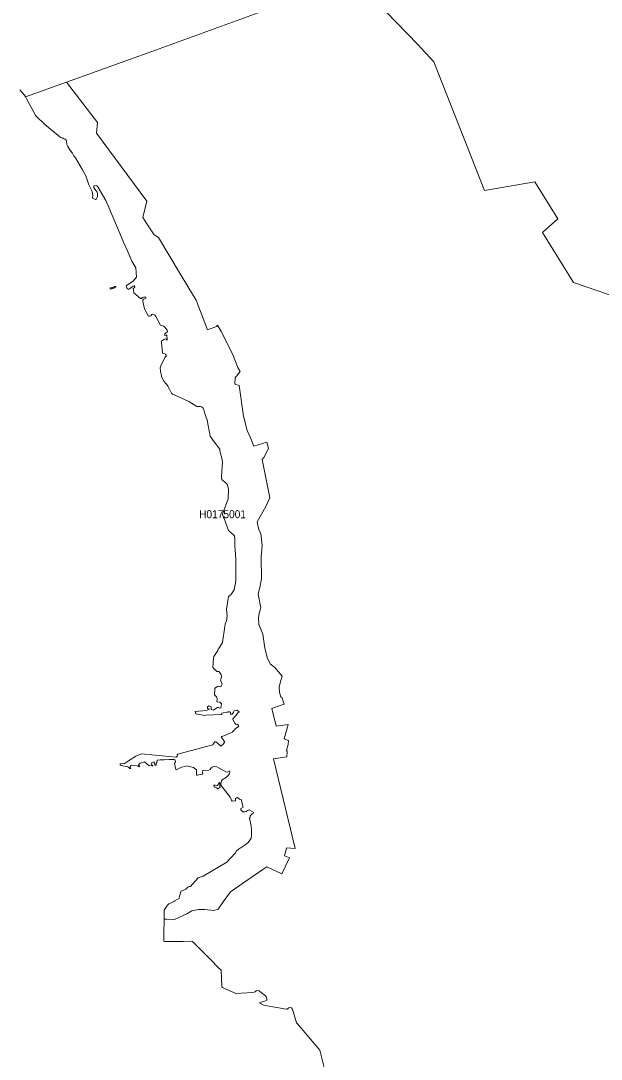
# Model space of a CAD drawing. Extents: x 369010 to 739155, y 6377141 to 6616555.
# Drawn here: x 408273 to 415523, y 6515962 to 6528935 of the extents above; entities that cross this region are included whole.
import ezdxf
from ezdxf.enums import TextEntityAlignment as Align

# ---------------------------------------------------------------- set-up
doc = ezdxf.new("R2010")
doc.units = 0
doc.header["$LTSCALE"] = 40
doc.layers.add('1', color=7, linetype='Continuous', lineweight=13)
doc.layers.add('2', color=7, linetype='Continuous')

msp = doc.modelspace()

# ---------------------------------------------------------------- linework, layer by layer
at = {"layer": '1'}
for points in [[(408261.96, 6528071.2), (408317.41, 6528003.84), (408332.3, 6527985.63), (408844.54, 6528170.01), (409956.56, 6528570.03), (412430.18, 6529472.36), (413231.39, 6528636.89), (413431.98, 6528420.25), (414063.54, 6526816.02), (414694.11, 6526922.93), (414982.91, 6526461.01), (414789.77, 6526292.2), (415176.55, 6525665.1), (415772.53, 6525459.71)], [(415772.53, 6525459.71), (415176.55, 6525665.1), (414789.77, 6526292.2), (414982.91, 6526461.01), (414694.11, 6526922.93), (414063.54, 6526816.02), (413431.98, 6528420.25), (413231.39, 6528636.89), (412430.18, 6529472.36), (409956.56, 6528570.03), (408844.54, 6528170.01)], [(408844.54, 6528170.01), (408332.3, 6527985.63), (408339.75, 6527966.77), (408462.22, 6527749.13), (408573.94, 6527637.91), (408758.97, 6527486.81), (408774.2, 6527476.71), (408789.75, 6527469.76), (408801.34, 6527468.27), (408816.9, 6527461.48), (408827.49, 6527454.2), (408839.41, 6527441.79), (408844.37, 6527430.86), (408850.16, 6527387.83), (408860.92, 6527363.84), (408893.53, 6527312.2), (408917.69, 6527280.26), (408936.23, 6527248.98), (408956.25, 6527223.32), (409044.47, 6527072.22), (409084.19, 6526996.09), (409123.91, 6526886.03), (409164.95, 6526804.43), (409171.9, 6526757.1), (409169.75, 6526720.03), (409176.21, 6526716.71), (409198.38, 6526705.13), (409205.5, 6526701.49), (409212.45, 6526702.32), (409220.06, 6526711.75), (409228.01, 6526729.46), (409233.14, 6526747.66), (409232.48, 6526776.63), (409228.34, 6526791.36), (409223.71, 6526800.46), (409214.6, 6526812.05), (409186.8, 6526849.45), (409184.48, 6526866.83), (409185.97, 6526871.13), (409192.09, 6526874.11), (409212.78, 6526876.92), (409223.04, 6526871.96), (409234.79, 6526859.54), (409335.75, 6526689.57), (409378.29, 6526592.59), (409547.43, 6526188.59), (409550.74, 6526179.16), (409603.54, 6526069.26), (409661.79, 6525930.24), (409710.45, 6525850.14), (409718.73, 6525732.3), (409693.74, 6525703.66), (409675.37, 6525681.32), (409592.45, 6525629.85), (409590.3, 6525621.74), (409592.78, 6525609.49), (409602.54, 6525589.96), (409606.19, 6525586.32), (409614.13, 6525583.01), (409624.39, 6525583.34), (409643.42, 6525593.6), (409648.55, 6525599.73), (409664.61, 6525613.47), (409678.01, 6525619.26), (409689.6, 6525622.07), (409695.23, 6525620.75), (409699.36, 6525617.44), (409698.87, 6525610.49), (409688.11, 6525598.57), (409676.03, 6525590.96), (409686.79, 6525536.67), (409767.72, 6525466), (409774.34, 6525463.85), (409781.12, 6525466.33), (409792.38, 6525477.92), (409806.61, 6525484.04), (409820.68, 6525485.86), (409832.26, 6525483.38), (409836.57, 6525478.25), (409835.24, 6525469.64), (409805.78, 6525456.24), (409797.84, 6525446.14), (409795.69, 6525434.89), (409800.32, 6525413.37), (409816.54, 6525336.25), (409858.74, 6525260.94), (409864.87, 6525250.68), (409871.49, 6525245.05), (409880.43, 6525244.23), (409895.98, 6525251.18), (409911.21, 6525263.76), (409919.98, 6525267.89), (409931.07, 6525267.4), (409948.78, 6525257.96), (409958.54, 6525241.41), (410018.95, 6525131.85), (410031.86, 6525127.88), (410056.19, 6525118.61), (410071.25, 6525108.35), (410101.7, 6525070.28)], [(410985.83, 6524604.55), (410917.8, 6524774.86), (410777.29, 6525055.05), (410731.94, 6525130.69), (410716.88, 6525115.63), (410607.15, 6525073.92), (410463.66, 6525443.49), (410357.74, 6525613.8), (410263.07, 6525772.68), (409994.62, 6526229.64), (409937.86, 6526259.92), (409873.64, 6526362.04), (409798, 6526475.58), (409847.16, 6526679.97), (409220.23, 6527529.01), (409231.48, 6527665.22), (408845.69, 6528168.35), (408844.54, 6528170.01)], [(408844.54, 6528170.01), (408845.69, 6528168.35), (409231.48, 6527665.22), (409220.23, 6527529.01), (409847.16, 6526679.97), (409798, 6526475.58), (409873.64, 6526362.04), (409937.86, 6526259.92), (409994.62, 6526229.64), (410263.07, 6525772.68), (410357.74, 6525613.8), (410463.66, 6525443.49), (410607.15, 6525073.92), (410716.88, 6525115.63), (410731.94, 6525130.69), (410777.29, 6525055.05), (410917.8, 6524774.86), (410985.83, 6524604.55), (411013.96, 6524555.73), (410950.24, 6524472.81), (410945.94, 6524395.85), (410999.23, 6524379.63), (411055.34, 6523994.34), (411102.67, 6523817.08), (411144.05, 6523725.23), (411182.61, 6523620.14), (411345.47, 6523671.94), (411367.64, 6523593.49), (411309.88, 6523479.46), (411286.22, 6523453.47), (411382.54, 6522976.66), (411333.39, 6522867.92), (411225.31, 6522675.27), (411244.51, 6522576.14), (411269.67, 6522527.97), (411287.38, 6522379.85), (411277.11, 6522234.7), (411279.93, 6521962.94), (411259.24, 6521856.36), (411240.04, 6521776.26), (411260.73, 6521665.2), (411271.16, 6521601.48), (411251.79, 6521534.12), (411243.02, 6521474.87), (411247.49, 6521391.95), (411296.31, 6521272.46), (411319.98, 6521096.2), (411355.4, 6520968.93), (411393.96, 6520899.25), (411447.25, 6520854.89), (411538.94, 6520748.14), (411516.43, 6520680.62), (411501.7, 6520608.13), (411504.68, 6520547.39), (411520.9, 6520486.65), (411532.82, 6520483.67), (411555, 6520422.93), (411562.44, 6520397.77), (411407.03, 6520342.99), (411461.65, 6520123.37), (411611.27, 6520142.57), (411560.95, 6519963.32), (411615.74, 6519944.13), (411614.25, 6519893.81), (411590.58, 6519819.67), (411602.33, 6519806.43), (411595.05, 6519741.22), (411429.21, 6519716.06), (411701.3, 6518595.1), (411590.25, 6518602.55), (411581.31, 6518550.75), (411568.07, 6518503.41), (411627.32, 6518479.58), (411532.65, 6518277.34), (411346.13, 6518366.21), (411310.55, 6518339.56), (411041.77, 6518157.51), (410893.64, 6518052.42), (410800.63, 6517926.8), (410740.05, 6517836.6), (410683.78, 6517818.89), (410572.73, 6517832.13), (410493.62, 6517833.78), (410409.21, 6517817.57), (410348.47, 6517780.49), (410194.55, 6517706.51), (410092.6, 6517712.14), (410062.15, 6517713.79), (410061.32, 6517528.93), (410058.01, 6517436.57), (410067.11, 6517433.93), (410300.14, 6517432.77), (410399.94, 6517438.56), (410416.99, 6517431.44), (410530.03, 6517322.21), (410643.56, 6517207.68), (410744.36, 6517105.4), (410777.13, 6517076.44), (410785.4, 6516868.57), (410794.17, 6516856.65)], [(410101.7, 6525070.28), (410105.68, 6525060.19), (410104.68, 6525051.08), (410098.73, 6525043.97), (410080.35, 6525032.38), (410070.92, 6525021.13), (410066.29, 6525011.2), (410068.11, 6525005.9), (410076.38, 6525001.93), (410089.79, 6525006.56), (410095.25, 6525011.2), (410103.36, 6524946.48), (410083.5, 6524960.22), (410067.94, 6524958.07), (410058.51, 6524954.1), (410031.86, 6524932.58), (410029.21, 6524923.15), (410030.04, 6524911.73), (410041.3, 6524791.24), (410044.61, 6524784.12), (410056.19, 6524778), (410074.89, 6524773.53), (410082.18, 6524767.08), (410087.31, 6524756.98), (410087.64, 6524745.23), (410078.2, 6524730.83), (410027.89, 6524636.66), (410014.48, 6524599.59), (410018.29, 6524559.04), (410029.21, 6524497.8), (410034.18, 6524479.1), (410060.99, 6524433.26), (410087.64, 6524399.33), (410103.86, 6524377.48), (410130.01, 6524332.96), (410147.71, 6524298.54), (410155.99, 6524281.99), (410168.57, 6524271.06), (410195.05, 6524256.5), (410200.18, 6524256.17), (410371.81, 6524178.21), (410473.92, 6524117.14), (410512.32, 6524117.14), (410529.86, 6524111.68), (410551.54, 6524094.97), (410559.16, 6524075.77), (410569.58, 6524041.67), (410586.63, 6523978.62), (410600.37, 6523949.65), (410611.46, 6523880.14), (410639.1, 6523744.93), (410687.42, 6523674.59), (410760.41, 6523584.39), (410759.91, 6523561.88), (410762.07, 6523546.65), (410786.73, 6523452.48), (410789.04, 6523438.08), (410793.68, 6523427.16), (410778.28, 6523241.63), (410779.77, 6523218.46), (410785.07, 6523206.54), (410794.5, 6523198.1), (410850.61, 6523145.64), (410867.99, 6523086.22), (410863.02, 6522964.74), (410795.33, 6522783.18), (410792.85, 6522771.27), (410794.67, 6522758.19), (410806.59, 6522728.57), (410813.37, 6522719.13), (410869.15, 6522566.87), (410940.48, 6522502.49), (410944.95, 6522456.48), (410947.76, 6522366.28), (410951.07, 6522327.88), (410953.22, 6522264.82), (410957.03, 6522207.56), (410957.03, 6522171.98), (410957.86, 6521939.61), (410939.98, 6521827.06), (410897.78, 6521762.19), (410885.03, 6521755.73), (410869.15, 6521740.84), (410842.5, 6521586.59), (410851.6, 6521497.55), (410843.16, 6521434.99), (410827.11, 6521407.02), (410823.8, 6521392.12), (410820.65, 6521366.8), (410792.35, 6521168.03), (410753.79, 6521105.96), (410739.06, 6521083.46), (410734.59, 6521068.73), (410682.29, 6520991.77), (410679.98, 6520976.37), (410671.7, 6520855.56), (410719.86, 6520807.23), (410730.29, 6520804.58), (410747.34, 6520805.57), (410757.1, 6520797.96)], [(411153.98, 6518796.36), (411155.97, 6518757.13), (411151.17, 6518725.52), (411144.05, 6518711.29), (411134.12, 6518699.7), (411114.59, 6518671.4), (411086.78, 6518648.06), (410986.16, 6518582.52), (410967.46, 6518563.82), (410951.24, 6518537.51), (410848.29, 6518422.15), (410550.88, 6518249.7), (410488.49, 6518226.86), (410416.99, 6518147.25), (410391.34, 6518120.6), (410376.28, 6518119.78), (410360.88, 6518110.84), (410334.73, 6518085.85), (410274.82, 6518063.34), (410272.34, 6518055.06), (410252.64, 6517981.91), (410253.47, 6517973.97), (410197.53, 6517940.87), (410192.57, 6517937.22), (410134.64, 6517907.27), (410123.55, 6517902.97), (410103.53, 6517885.92), (410071.09, 6517838.42), (410062.48, 6517826.01), (410062.15, 6517713.79), (410092.6, 6517712.14), (410194.55, 6517706.51), (410348.47, 6517780.49), (410409.21, 6517817.57), (410493.62, 6517833.78), (410572.73, 6517832.13), (410683.78, 6517818.89), (410740.05, 6517836.6), (410800.63, 6517926.8), (410893.64, 6518052.42), (411041.77, 6518157.51), (411310.55, 6518339.56), (411346.13, 6518366.21), (411532.65, 6518277.34), (411627.32, 6518479.58), (411568.07, 6518503.41), (411581.31, 6518550.75), (411590.25, 6518602.55), (411701.3, 6518595.1), (411429.21, 6519716.06), (411595.05, 6519741.22), (411602.33, 6519806.43), (411590.58, 6519819.67), (411614.25, 6519893.81), (411615.74, 6519944.13), (411560.95, 6519963.32), (411611.27, 6520142.57), (411461.65, 6520123.37), (411407.03, 6520342.99), (411562.44, 6520397.77), (411555, 6520422.93), (411532.82, 6520483.67), (411520.9, 6520486.65), (411504.68, 6520547.39), (411501.7, 6520608.13), (411516.43, 6520680.62), (411538.94, 6520748.14), (411447.25, 6520854.89), (411393.96, 6520899.25), (411355.4, 6520968.93), (411319.98, 6521096.2), (411296.31, 6521272.46), (411247.49, 6521391.95), (411243.02, 6521474.87), (411251.79, 6521534.12), (411271.16, 6521601.48), (411260.73, 6521665.2), (411240.04, 6521776.26), (411259.24, 6521856.36), (411279.93, 6521962.94), (411277.11, 6522234.7), (411287.38, 6522379.85), (411269.67, 6522527.97), (411244.51, 6522576.14), (411225.31, 6522675.27), (411333.39, 6522867.92), (411382.54, 6522976.66), (411286.22, 6523453.47), (411309.88, 6523479.46), (411367.64, 6523593.49), (411345.47, 6523671.94), (411182.61, 6523620.14), (411144.05, 6523725.23), (411102.67, 6523817.08), (411055.34, 6523994.34), (410999.23, 6524379.63), (410945.94, 6524395.85), (410950.24, 6524472.81), (411013.96, 6524555.73), (410985.83, 6524604.55)], [(410757.1, 6520797.96), (410767.53, 6520777.6), (410776.96, 6520765.03), (410780.77, 6520748.48), (410777.46, 6520717.69), (410768.19, 6520701.8), (410769.68, 6520688.4), (410788.88, 6520646.69), (410772.33, 6520614.75), (410745.52, 6520621.37), (410730.62, 6520616.9), (410696.86, 6520596.05), (410695.86, 6520585.62), (410694.21, 6520513.79), (410721.68, 6520483.5), (410724.33, 6520460.5), (410722.18, 6520425.91), (410758.42, 6520423.09), (410779.28, 6520401.74), (410777.13, 6520378.08), (410771.5, 6520351.1), (410760.58, 6520347.29), (410748.99, 6520350.11), (410741.87, 6520357.22), (410728.8, 6520356.56), (410698.51, 6520334.05), (410680.97, 6520324.29), (410651.84, 6520333.06), (410651.84, 6520355.07), (410650.18, 6520363.18), (410623.87, 6520376.42), (410605.17, 6520363.84), (410604.67, 6520348.45), (410611.79, 6520340.67), (410628.34, 6520333.56), (410588.45, 6520317.17), (410452.74, 6520305.59), (410458.37, 6520278.61), (410566.44, 6520254.45), (410580.18, 6520259.91), (410781.43, 6520267.69), (410785.9, 6520273.64), (410785.9, 6520284.73), (410800.13, 6520289.7), (410846.8, 6520296.81), (410859.38, 6520296.81), (410864.84, 6520302.28), (410879.74, 6520303.44), (410891.32, 6520298.47), (410893.48, 6520289.7), (410890.66, 6520276.46), (410895.63, 6520271), (410905.06, 6520269.84), (410914.83, 6520273.64), (410930.55, 6520294.5), (410933.36, 6520308.9), (410940.98, 6520316.51), (410971.76, 6520324.79), (411000.23, 6520300.12), (410985.99, 6520289.04), (410979.87, 6520280.26), (410934.36, 6520225.32), (410923.43, 6520216.05), (410923.43, 6520206.12), (410948.09, 6520158.45), (410958.52, 6520149.02), (410972.26, 6520143.56), (410981.52, 6520142.4), (410992.28, 6520134.79), (410994.43, 6520120.55), (410951.73, 6520088.61), (410946.77, 6520081.99), (410918.8, 6520051.87), (410916.48, 6520048.06), (410790.2, 6519995.76), (410778.95, 6519994.94), (410774.31, 6519989.81), (410814.2, 6519935.19), (410819, 6519930.55), (410818.17, 6519921.12), (410804.93, 6519903.25), (410772, 6519871.97), (410720.69, 6519919.3), (410709.77, 6519927.74), (410696.36, 6519927.41), (410673.85, 6519889.01), (410264.56, 6519782.93), (410233.78, 6519773.16), (410227.65, 6519764.39), (410228.81, 6519746.18), (410208.12, 6519733.77), (410121.07, 6519742.71), (409780.96, 6519776.47), (409708.14, 6519749.82), (409606.85, 6519679.98), (409568.12, 6519655.49), (409515.49, 6519653.67), (409514.99, 6519641.09), (409526.74, 6519631.16), (409610.82, 6519613.28)], [(409610.82, 6519613.28), (409621.58, 6519608.32), (409633.49, 6519592.43), (409643.92, 6519590.77), (409644.09, 6519603.68), (409639.12, 6519615.27), (409641.44, 6519629.17), (409656, 6519635.79), (409726.01, 6519629.01), (409740.57, 6519624.87), (409753.48, 6519614.94), (409758.95, 6519617.09), (409745.37, 6519637.78), (409749.68, 6519649.2), (409763.75, 6519659.13), (409817.53, 6519676.67), (409876.78, 6519627.02), (409898.13, 6519635.79), (409922.79, 6519624.54), (409923.62, 6519630.66), (409908.73, 6519641.92), (409904.92, 6519653.67), (409908.56, 6519665.25), (409939.51, 6519677.5), (409948.28, 6519641.58), (409958.71, 6519630.83), (409963.67, 6519641.92), (409965.66, 6519657.14), (409971.62, 6519669.22), (409975.92, 6519697.03), (410015.48, 6519704.48), (410063.97, 6519704.48), (410126.86, 6519707.46), (410186.94, 6519706.3), (410203.32, 6519696.53), (410207.46, 6519677.83), (410191.9, 6519655.82), (410208.12, 6519582.83), (410216.07, 6519577.37), (410256.29, 6519599.55), (410279.79, 6519609.15), (410324.14, 6519620.4), (410345.99, 6519626.19), (410428.24, 6519606.17), (410467.3, 6519577.37), (410468.96, 6519511.17), (410475.91, 6519509.02), (410538.64, 6519522.92), (410547.08, 6519531.19), (410538.64, 6519553.7), (410546.25, 6519568.27), (410555.35, 6519570.42), (410623.54, 6519573.56), (410637.28, 6519579.85), (410656.31, 6519604.84), (410682.13, 6519619.9), (410723.67, 6519616.26), (410804.43, 6519571.08), (410835.22, 6519550.72), (410849.62, 6519548.74), (410879.57, 6519564.96), (410885.37, 6519558.17), (410885.03, 6519548.57), (410878.75, 6519533.18), (410866.66, 6519511.99), (410841.51, 6519484.02), (410790.2, 6519454.4), (410781.76, 6519439.5), (410771.33, 6519400.78), (410773.15, 6519385.88), (410887.19, 6519234.94), (410905.89, 6519198.2), (410914.83, 6519187.11), (410949.42, 6519191.58), (410956.7, 6519195.88), (410955.87, 6519219.55), (410967.95, 6519229.48), (410981.85, 6519229.98), (411005.19, 6519209.62), (411027.37, 6519207.8), (411049.88, 6519112.8), (411020.25, 6519093.27), (411019.59, 6519087.48), (411019.59, 6519076.22), (411037.96, 6519062.49), (411045.9, 6519054.54), (411070.07, 6519051.23), (411087.78, 6519058.35), (411112.77, 6519075.4), (411127.17, 6519076.72), (411184.1, 6519044.61), (411180.46, 6519036.67), (411161.43, 6519027.07), (411138.09, 6519000.92), (411137.26, 6518987.51), (411131.8, 6518974.6), (411149.51, 6518878.78), (411150.01, 6518862.06), (411154.64, 6518834.26), (411153.98, 6518796.36)], [(410794.17, 6516856.65), (410818.34, 6516846.22), (410960.84, 6516784.82), (411024.06, 6516787.3), (411171.52, 6516795.91), (411199.33, 6516802.53), (411215.05, 6516814.94), (411233.92, 6516819.08), (411249.64, 6516815.77), (411260.07, 6516809.48), (411328.42, 6516756.19), (411337.52, 6516743.61), (411344.64, 6516717.79), (411345.47, 6516700.91), (411308.06, 6516683.7), (411259.74, 6516669.96), (411260.89, 6516661.69), (411310.71, 6516637.52), (411328.92, 6516633.71), (411419.45, 6516617.99), (411591.74, 6516588.37), (411602, 6516588.2), (411619.87, 6516605.08), (411634.77, 6516609.05), (411652.31, 6516602.93), (411665.22, 6516588.37), (411718.02, 6516418.73), (411730.93, 6516403), (412007.81, 6516076.79), (412063.42, 6515859.49)]]:
    msp.add_lwpolyline(points, dxfattribs=at)
for points in [[(409444.98, 6525615.12), (409419.83, 6525602.87), (409391.36, 6525600.72), (409387.72, 6525595.26), (409388.38, 6525588.64), (409400.96, 6525583.34), (409420.32, 6525595.92), (409436.88, 6525593.77), (409461.54, 6525609.99), (409461.54, 6525613.63), (409457.23, 6525615.45)], [(410757.27, 6519418.98), (410751.31, 6519416.66), (410732.11, 6519382.9), (410721.68, 6519377.11), (410692.72, 6519390.02), (410683.45, 6519387.87), (410684.61, 6519376.12), (410698.51, 6519360.72), (410719.37, 6519353.28), (410735.09, 6519338.22), (410741.87, 6519338.38), (410746.34, 6519348.97), (410760.08, 6519355.26), (410763.89, 6519362.05), (410758.92, 6519372.81), (410760.91, 6519412.53)]]:
    msp.add_lwpolyline(points, close=True, dxfattribs=at)

# ---------------------------------------------------------------- texts
at = {"layer": '2', "width": 0.95}
msp.add_text('H0175001', height=100, dxfattribs=at).set_placement((410792.84, 6522721.26), align=Align.CENTER)

doc.saveas('drawing.dxf')
